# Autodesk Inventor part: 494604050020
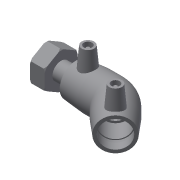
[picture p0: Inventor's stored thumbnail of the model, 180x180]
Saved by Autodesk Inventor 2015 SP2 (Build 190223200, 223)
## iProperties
Created: 2017-06
Part Number: 494604050020
Material: Generic
Description: PLASSON 45° ELBOW FEMALE FREE NUT TRANSITION 50-2"
Document SubType Name: Modeling
Designer: KIM
Mass: 55.0731 g
Surface Area: 148.067 cm^2
Volume: 55.0731 cm^3
Density: 1 g/cm^3
Appearance: Default
Author: KIM
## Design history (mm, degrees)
derived "494604.ipt"
feature "Solid1::494604.ipt"
tag "TaggingFeature1"
body "Solid1"
other parameters: "d2" = 67, "d4" = 31.25, "d5" = 60.3, "d8" = 168 deg, "d10" = 19.6, "d11" = 6.53333, "d29" = 51, "d30" = 15, "d31" = 43.75, "d34" = 5 deg, "d41" = 4, "d42" = 14, "d43" = 0, "d50" = 42.5, "d51" = 19.6, "d52" = 49.49, "d54" = 135 deg, "d86" = 30.15, "d87" = 135 deg, "d88" = 125, "d90" = 49, "d91" = 0, "d92" = 49, "d93" = 0, "d101" = 3, "d102" = 0, "d108" = 38, "d110" = 41, "d112" = 84.984, "d113" = 56.656, "d139" = 39.6592, "d140" = 38, "d141" = 20.5, "d142" = 2.05, "d143" = 4.1, "d144" = 16.4, "d145" = 45.3248, "d146" = 2.8328, "d150" = 0, "d151" = 2.5, "L_" = 166, "L_1" = 49, "D_" = 38, "A_" = 51, "d_2" = 12, "L_2" = 41, "G_" = 56.656, "D_1" = 67
